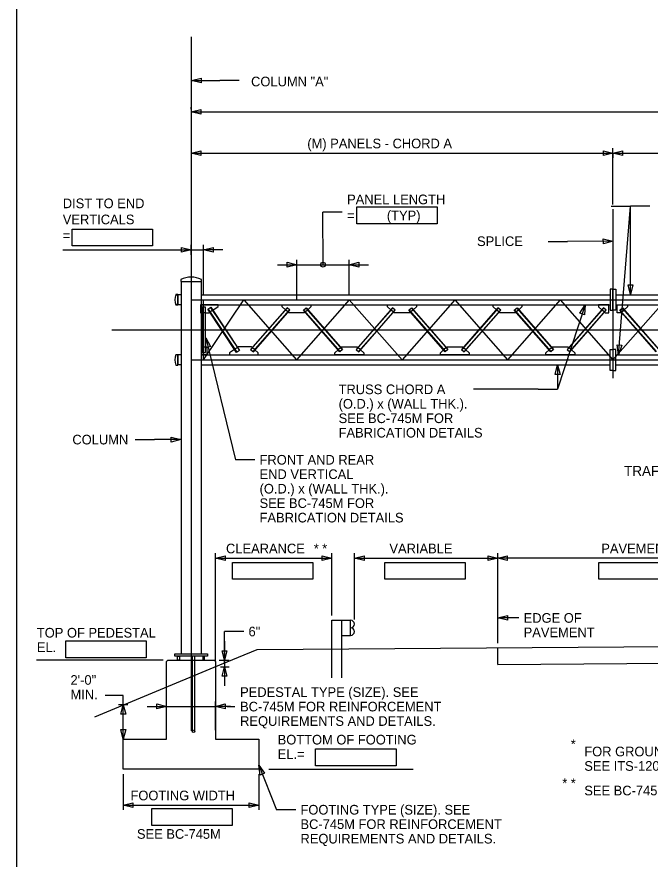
# Model space of a CAD drawing. Extents: x 3831399 to 3833095, y 499014 to 500202.
# Drawn here: x 3832280.2 to 3832471.3, y 499739.8 to 499994 of the extents above; entities that cross this region are included whole.
import ezdxf

# ---------------------------------------------------------------- set-up
doc = ezdxf.new("R2010")
doc.units = 0
for name, color, linetype in [('0-ANCHOR', 7, 'Continuous'), ('0-foundation', 7, 'Continuous'), ('0-truss', 7, 'Continuous'), ('2', 7, 'Continuous'), ('CenterLine', 7, 'Continuous'), ('Default', 7, 'Continuous'), ('DIM TXT', 7, 'Continuous'), ('grade', 7, 'Continuous'), ('x-grail', 7, 'Continuous')]:
    doc.layers.add(name, color=color, linetype=linetype)

msp = doc.modelspace()

# ---------------------------------------------------------------- linework, layer by layer
at = {"layer": '0-ANCHOR'}
for p, q in [((3832328.66, 499801.04), (3832329.23, 499801.04)), ((3832328.66, 499799.81), (3832328.66, 499801.04)), ((3832329.23, 499799.81), (3832328.66, 499799.81)), ((3832329.23, 499801.04), (3832329.23, 499799.81)), ((3832336.81, 499801.04), (3832336.24, 499801.04)), ((3832336.24, 499801.04), (3832336.24, 499799.81)), ((3832336.24, 499799.81), (3832336.81, 499799.81)), ((3832336.81, 499799.81), (3832336.81, 499801.04))]:
    msp.add_line(p, q, dxfattribs=at)
at = {"layer": '0-foundation'}
for p, q in [((3832325.35, 499799.43), (3832325.73, 499799.81)), ((3832325.35, 499797.87), (3832325.35, 499799.43)), ((3832325.73, 499799.81), (3832339.75, 499799.81)), ((3832333.12, 499778.39), (3832333.12, 499801.04)), ((3832333.87, 499778.39), (3832333.87, 499801.04)), ((3832339.75, 499799.81), (3832340.12, 499799.43)), ((3832340.12, 499799.43), (3832340.12, 499797.71)), ((3832325.35, 499776.02), (3832325.35, 499797.87)), ((3832340.12, 499797.71), (3832340.12, 499776.02)), ((3832312.28, 499766.93), (3832312.28, 499776.02)), ((3832312.28, 499776.02), (3832325.35, 499776.02)), ((3832340.12, 499776.02), (3832353.2, 499776.02)), ((3832353.2, 499776.02), (3832353.2, 499766.93)), ((3832353.2, 499766.93), (3832312.28, 499766.93))]:
    msp.add_line(p, q, dxfattribs=at)
msp.add_circle((3832333.49, 499778.39), 0.379, dxfattribs=at)
at = {"layer": '0-truss'}
for p, q in [((3832329.63, 499914.72), (3832329.63, 499914.15)), ((3832329.63, 499914.15), (3832335.84, 499914.15)), ((3832329.71, 499914.15), (3832329.71, 499801.79)), ((3832335.77, 499914.15), (3832335.77, 499801.79)), ((3832335.84, 499914.15), (3832335.84, 499914.72)), ((3832460.05, 499911.79), (3832459.19, 499911.79)), ((3832459.19, 499911.79), (3832459.19, 499905.49)), ((3832460.05, 499905.49), (3832460.05, 499911.79)), ((3832460.05, 499905.49), (3832460.05, 499911.79)), ((3832460.05, 499911.79), (3832460.9, 499911.79)), ((3832460.9, 499911.79), (3832460.9, 499905.49)), ((3832328.74, 499910.23), (3832328.17, 499910.23)), ((3832328.19, 499910.16), (3832328.74, 499910.16)), ((3832329.71, 499910.16), (3832328.74, 499910.16)), ((3832328.74, 499910.16), (3832328.74, 499907.13)), ((3832335.77, 499910.16), (3832459.19, 499910.16)), ((3832460.9, 499910.16), (3832537.29, 499910.16)), ((3832328.74, 499907.13), (3832328.19, 499907.13)), ((3832329.71, 499907.13), (3832328.74, 499907.13)), ((3832335.77, 499907.13), (3832459.19, 499907.13)), ((3832337.07, 499906.37), (3832335.98, 499906.37)), ((3832335.98, 499906.37), (3832335.98, 499892.73)), ((3832336.06, 499906.37), (3832336.06, 499892.73)), ((3832336.99, 499906.37), (3832336.99, 499892.73)), ((3832337.07, 499892.73), (3832337.07, 499906.37)), ((3832337.79, 499905.77), (3832338.7, 499906.37)), ((3832338.63, 499906.33), (3832347.32, 499893.29)), ((3832338.7, 499906.37), (3832347.39, 499893.33)), ((3832339.29, 499905.47), (3832340.91, 499906.55)), ((3832361.69, 499906.18), (3832350.71, 499893.63)), ((3832350.76, 499893.58), (3832361.74, 499906.13)), ((3832361.19, 499905.62), (3832360.21, 499906.48)), ((3832362.51, 499905.47), (3832361.69, 499906.18)), ((3832366.62, 499905.47), (3832367.44, 499906.18)), ((3832367.38, 499906.13), (3832378.36, 499893.58)), ((3832367.44, 499906.18), (3832378.42, 499893.63)), ((3832368.92, 499906.48), (3832367.94, 499905.62)), ((3832393.51, 499906.18), (3832382.53, 499893.63)), ((3832393.57, 499906.13), (3832382.59, 499893.58)), ((3832393.02, 499905.62), (3832392.03, 499906.48)), ((3832394.33, 499905.47), (3832393.51, 499906.18)), ((3832398.45, 499905.47), (3832399.27, 499906.18)), ((3832399.21, 499906.13), (3832410.19, 499893.58)), ((3832399.27, 499906.18), (3832410.25, 499893.63)), ((3832400.75, 499906.48), (3832399.76, 499905.62)), ((3832425.34, 499906.18), (3832414.36, 499893.63)), ((3832425.4, 499906.13), (3832414.42, 499893.58)), ((3832424.85, 499905.62), (3832423.86, 499906.48)), ((3832426.16, 499905.47), (3832425.34, 499906.18)), ((3832430.27, 499905.47), (3832431.09, 499906.18)), ((3832431.04, 499906.13), (3832442.02, 499893.58)), ((3832431.09, 499906.18), (3832442.07, 499893.63)), ((3832432.58, 499906.48), (3832431.59, 499905.62)), ((3832457.17, 499906.18), (3832446.19, 499893.63)), ((3832457.23, 499906.13), (3832446.25, 499893.58)), ((3832455.69, 499906.48), (3832456.67, 499905.62)), ((3832457.99, 499905.47), (3832457.17, 499906.18)), ((3832458.81, 499904.71), (3832458.81, 499907.13)), ((3832460.9, 499907.13), (3832537.29, 499907.13)), ((3832461.28, 499904.71), (3832461.28, 499907.13)), ((3832462.1, 499905.47), (3832462.92, 499906.18)), ((3832462.86, 499906.13), (3832473.84, 499893.58)), ((3832462.92, 499906.18), (3832473.9, 499893.63)), ((3832464.4, 499906.48), (3832463.42, 499905.62)), ((3832337.07, 499904.71), (3832335.98, 499904.71)), ((3832346.48, 499892.73), (3832337.79, 499905.77)), ((3832337.85, 499905.81), (3832346.54, 499892.77)), ((3832338.15, 499904.71), (3832338.39, 499904.87)), ((3832339.29, 499905.47), (3832338.39, 499904.87)), ((3832351.47, 499892.97), (3832362.45, 499905.52)), ((3832351.53, 499892.92), (3832362.51, 499905.47)), ((3832362.01, 499904.9), (3832361.19, 499905.62)), ((3832362.23, 499904.71), (3832362.01, 499904.9)), ((3832377.6, 499892.92), (3832366.62, 499905.47)), ((3832366.68, 499905.52), (3832377.66, 499892.97)), ((3832367.12, 499904.9), (3832366.9, 499904.71)), ((3832367.94, 499905.62), (3832367.12, 499904.9)), ((3832394.28, 499905.52), (3832383.3, 499892.97)), ((3832383.35, 499892.92), (3832394.33, 499905.47)), ((3832393.84, 499904.9), (3832393.02, 499905.62)), ((3832394.05, 499904.71), (3832393.84, 499904.9)), ((3832409.43, 499892.92), (3832398.45, 499905.47)), ((3832398.51, 499905.52), (3832409.49, 499892.97)), ((3832398.94, 499904.9), (3832398.73, 499904.71)), ((3832399.76, 499905.62), (3832398.94, 499904.9)), ((3832426.1, 499905.52), (3832415.12, 499892.97)), ((3832415.18, 499892.92), (3832426.16, 499905.47)), ((3832425.67, 499904.9), (3832424.85, 499905.62)), ((3832425.88, 499904.71), (3832425.67, 499904.9)), ((3832441.25, 499892.92), (3832430.27, 499905.47)), ((3832430.33, 499905.52), (3832441.31, 499892.97)), ((3832430.77, 499904.9), (3832430.56, 499904.71)), ((3832431.59, 499905.62), (3832430.77, 499904.9)), ((3832457.93, 499905.52), (3832446.95, 499892.97)), ((3832447.01, 499892.92), (3832457.99, 499905.47)), ((3832457.49, 499904.9), (3832456.67, 499905.62)), ((3832457.49, 499904.9), (3832457.71, 499904.71)), ((3832457.71, 499904.71), (3832458.81, 499904.71)), ((3832458.81, 499904.71), (3832458.81, 499904.71)), ((3832459.19, 499905.49), (3832460.05, 499905.49)), ((3832460.9, 499905.49), (3832460.05, 499905.49)), ((3832462.38, 499904.71), (3832461.28, 499904.71)), ((3832461.28, 499904.71), (3832461.28, 499904.71)), ((3832473.08, 499892.92), (3832462.1, 499905.47)), ((3832462.16, 499905.52), (3832473.14, 499892.97)), ((3832462.6, 499904.9), (3832462.38, 499904.71)), ((3832462.6, 499904.9), (3832463.42, 499905.62)), ((3832335.77, 499894.39), (3832335.98, 499894.39)), ((3832335.98, 499894.39), (3832337.07, 499894.39)), ((3832337.07, 499894.39), (3832337.45, 499894.39)), ((3832337.45, 499894.39), (3832337.45, 499891.97)), ((3832345.88, 499893.63), (3832344.29, 499892.57)), ((3832346.79, 499894.23), (3832345.88, 499893.63)), ((3832347.39, 499893.33), (3832346.48, 499892.73)), ((3832347.03, 499894.39), (3832346.79, 499894.23)), ((3832350.99, 499894.39), (3832347.03, 499894.39)), ((3832350.71, 499893.63), (3832351.53, 499892.92)), ((3832351.2, 499894.2), (3832350.99, 499894.39)), ((3832352.02, 499893.48), (3832351.2, 499894.2)), ((3832353.01, 499892.62), (3832352.02, 499893.48)), ((3832376.12, 499892.62), (3832377.11, 499893.48)), ((3832377.92, 499894.2), (3832377.11, 499893.48)), ((3832378.42, 499893.63), (3832377.6, 499892.92)), ((3832377.92, 499894.2), (3832378.14, 499894.39)), ((3832382.53, 499893.63), (3832383.35, 499892.92)), ((3832382.82, 499894.39), (3832383.03, 499894.2)), ((3832383.85, 499893.48), (3832383.03, 499894.2)), ((3832383.85, 499893.48), (3832384.83, 499892.62)), ((3832407.95, 499892.62), (3832408.93, 499893.48)), ((3832409.75, 499894.2), (3832408.93, 499893.48)), ((3832410.25, 499893.63), (3832409.43, 499892.92)), ((3832409.75, 499894.2), (3832409.97, 499894.39)), ((3832414.36, 499893.63), (3832415.18, 499892.92)), ((3832414.64, 499894.39), (3832414.86, 499894.2)), ((3832415.68, 499893.48), (3832414.86, 499894.2)), ((3832415.68, 499893.48), (3832416.66, 499892.62)), ((3832439.77, 499892.62), (3832440.76, 499893.48)), ((3832441.58, 499894.2), (3832440.76, 499893.48)), ((3832442.07, 499893.63), (3832441.25, 499892.92)), ((3832441.58, 499894.2), (3832441.79, 499894.39)), ((3832446.19, 499893.63), (3832447.01, 499892.92)), ((3832446.47, 499894.39), (3832446.68, 499894.2)), ((3832447.5, 499893.48), (3832446.68, 499894.2)), ((3832447.5, 499893.48), (3832448.49, 499892.62)), ((3832459.19, 499893.61), (3832460.05, 499893.61)), ((3832459.19, 499887.31), (3832459.19, 499893.61)), ((3832460.05, 499893.61), (3832460.05, 499887.31)), ((3832460.9, 499893.61), (3832460.05, 499893.61)), ((3832460.05, 499893.61), (3832460.05, 499887.31)), ((3832460.9, 499887.31), (3832460.9, 499893.61)), ((3832328.74, 499892.04), (3832328.17, 499892.04)), ((3832329.71, 499891.97), (3832328.74, 499891.97)), ((3832328.74, 499891.97), (3832328.74, 499888.94)), ((3832335.77, 499891.97), (3832459.19, 499891.97)), ((3832337.45, 499891.97), (3832335.77, 499891.97)), ((3832335.98, 499892.73), (3832337.07, 499892.73)), ((3832460.9, 499891.97), (3832537.29, 499891.97)), ((3832329.71, 499888.94), (3832328.74, 499888.94)), ((3832335.77, 499888.94), (3832459.19, 499888.94)), ((3832460.9, 499888.94), (3832537.29, 499888.94)), ((3832460.05, 499887.31), (3832459.19, 499887.31)), ((3832460.05, 499887.31), (3832460.9, 499887.31)), ((3832327.81, 499801.04), (3832327.81, 499801.79)), ((3832327.81, 499801.79), (3832337.66, 499801.79)), ((3832337.66, 499801.79), (3832337.66, 499801.04)), ((3832337.66, 499801.04), (3832327.81, 499801.04))]:
    msp.add_line(p, q, dxfattribs=at)
for points in [[(3832328.17, 499907.06), (3832328.74, 499907.06), (3832328.74, 499910.23)], [(3832340.91, 499906.55), (3832340.91, 499907.13), (3832335.6, 499907.13), (3832335.6, 499904.71), (3832335.98, 499904.71)], [(3832360.21, 499906.48), (3832360.21, 499907.13), (3832368.92, 499907.13), (3832368.92, 499906.48)], [(3832392.03, 499906.48), (3832392.03, 499907.13), (3832400.75, 499907.13), (3832400.75, 499906.48)], [(3832423.86, 499906.48), (3832423.86, 499907.13), (3832432.58, 499907.13), (3832432.58, 499906.48)], [(3832458.81, 499907.13), (3832455.69, 499907.13), (3832455.69, 499906.48)], [(3832461.28, 499907.13), (3832464.4, 499907.13), (3832464.4, 499906.48)], [(3832337.07, 499904.71), (3832338.15, 499904.71)], [(3832366.9, 499904.71), (3832362.23, 499904.71)], [(3832398.73, 499904.71), (3832394.05, 499904.71)], [(3832430.56, 499904.71), (3832425.88, 499904.71)], [(3832378.14, 499894.39), (3832382.82, 499894.39)], [(3832409.97, 499894.39), (3832414.64, 499894.39)], [(3832441.79, 499894.39), (3832446.47, 499894.39)], [(3832328.17, 499888.87), (3832328.74, 499888.87), (3832328.74, 499892.04)], [(3832344.29, 499892.57), (3832344.29, 499891.97), (3832353.01, 499891.97), (3832353.01, 499892.62)], [(3832384.83, 499892.62), (3832384.83, 499891.97), (3832376.12, 499891.97), (3832376.12, 499892.62)], [(3832416.66, 499892.62), (3832416.66, 499891.97), (3832407.95, 499891.97), (3832407.95, 499892.62)], [(3832448.49, 499892.62), (3832448.49, 499891.97), (3832439.77, 499891.97), (3832439.77, 499892.62)]]:
    msp.add_lwpolyline(points, dxfattribs=at)
for centre, radius, start, end in [((3832332.74, 499908.65), 6.82, 62.944, 117.056), ((3832331.28, 499908.64), 3.49, 152.944, 207.056), ((3832331.28, 499890.46), 3.49, 152.944, 207.056)]:
    msp.add_arc(centre, radius, start, end, dxfattribs=at)
at = {"layer": '2'}
msp.add_line((3832280.16, 499623.03), (3832280.16, 500187.03), dxfattribs=at)
at = {"layer": 'CenterLine'}
for p, q in [((3832332.74, 499988), (3832332.74, 499778.49)), ((3832460.05, 499935.93), (3832460.05, 499885)), ((3832332.74, 499908.64), (3832746.49, 499908.64)), ((3832336.53, 499890.46), (3832348.65, 499908.64)), ((3832336.53, 499890.46), (3832336.53, 499908.64)), ((3832348.65, 499908.64), (3832364.56, 499890.46)), ((3832380.48, 499908.64), (3832364.56, 499890.46)), ((3832380.48, 499908.64), (3832396.39, 499890.46)), ((3832412.3, 499908.64), (3832396.39, 499890.46)), ((3832412.3, 499908.64), (3832428.22, 499890.46)), ((3832444.13, 499908.64), (3832428.22, 499890.46)), ((3832444.13, 499908.64), (3832460.05, 499890.46)), ((3832475.96, 499908.64), (3832460.05, 499890.46)), ((3832308.87, 499899.55), (3832771.9, 499899.55)), ((3832332.74, 499890.46), (3832746.49, 499890.46))]:
    msp.add_line(p, q, dxfattribs=at)
at = {"layer": 'Default'}
for p, q in [((3832382.75, 499936.68), (3832407, 499936.68)), ((3832382.75, 499931.58), (3832382.75, 499936.68)), ((3832407, 499936.68), (3832407, 499931.58)), ((3832407, 499931.58), (3832382.75, 499931.58)), ((3832296.89, 499929.96), (3832321.14, 499929.96)), ((3832296.89, 499924.87), (3832296.89, 499929.96)), ((3832321.14, 499929.96), (3832321.14, 499924.87)), ((3832321.14, 499924.87), (3832296.89, 499924.87)), ((3832345.2, 499829.38), (3832369.45, 499829.38)), ((3832345.2, 499824.29), (3832345.2, 499829.38)), ((3832369.45, 499829.38), (3832369.45, 499824.29)), ((3832391.2, 499829.38), (3832415.45, 499829.38)), ((3832391.2, 499824.29), (3832391.2, 499829.38)), ((3832415.45, 499829.38), (3832415.45, 499824.29)), ((3832455.78, 499829.38), (3832480.03, 499829.38)), ((3832455.78, 499824.29), (3832455.78, 499829.38)), ((3832369.45, 499824.29), (3832345.2, 499824.29)), ((3832415.45, 499824.29), (3832391.2, 499824.29)), ((3832480.03, 499824.29), (3832455.78, 499824.29)), ((3832294.94, 499805.68), (3832319.19, 499805.68)), ((3832294.94, 499800.58), (3832294.94, 499805.68)), ((3832319.19, 499805.68), (3832319.19, 499800.58)), ((3832324.27, 499799.88), (3832286.07, 499799.88)), ((3832319.19, 499800.58), (3832294.94, 499800.58)), ((3832370.33, 499773.07), (3832394.58, 499773.07)), ((3832370.33, 499767.98), (3832370.33, 499773.07)), ((3832394.58, 499773.07), (3832394.58, 499767.98)), ((3832356.17, 499766.94), (3832399.76, 499766.94)), ((3832394.58, 499767.98), (3832370.33, 499767.98)), ((3832320.92, 499755.07), (3832345.17, 499755.07)), ((3832320.92, 499749.98), (3832320.92, 499755.07)), ((3832345.17, 499755.07), (3832345.17, 499749.98)), ((3832345.17, 499749.98), (3832320.92, 499749.98))]:
    msp.add_line(p, q, dxfattribs=at)
at = {"layer": 'DIM TXT'}
for p, q in [((3832332.83, 499974.77), (3832341.43, 499974.82)), ((3832347.25, 499974.82), (3832341.43, 499974.82)), ((3832332.74, 499966.13), (3832332.74, 499966.8)), ((3832332.74, 499965.35), (3832746.37, 499965.35)), ((3832332.74, 499962.44), (3832332.74, 499951.43)), ((3832460.05, 499937.39), (3832460.05, 499954.34)), ((3832332.74, 499952.88), (3832460.05, 499952.88)), ((3832460.05, 499952.88), (3832619.18, 499952.88)), ((3832460.05, 499952.88), (3832460.05, 499951.43)), ((3832459.5, 499936.87), (3832465.32, 499936.87)), ((3832461.75, 499892.03), (3832465.32, 499936.87)), ((3832465.35, 499910.18), (3832465.32, 499936.87)), ((3832471.14, 499936.87), (3832465.32, 499936.87)), ((3832378.36, 499935.08), (3832372.54, 499935.08)), ((3832372.56, 499919.22), (3832372.54, 499935.08)), ((3832440.48, 499926.24), (3832446.3, 499926.24)), ((3832460.05, 499926.27), (3832446.3, 499926.24)), ((3832294.02, 499923.7), (3832332.74, 499923.7)), ((3832329.83, 499924.43), (3832332.74, 499923.7)), ((3832329.83, 499922.97), (3832329.83, 499924.43)), ((3832332.74, 499923.7), (3832329.83, 499922.97)), ((3832332.74, 499922.21), (3832332.74, 499925.16)), ((3832332.74, 499923.7), (3832336.53, 499923.7)), ((3832336.53, 499910.1), (3832336.53, 499925.16)), ((3832336.53, 499923.7), (3832339.44, 499924.43)), ((3832342.35, 499923.7), (3832336.53, 499923.7)), ((3832339.44, 499922.97), (3832336.53, 499923.7)), ((3832339.44, 499924.43), (3832339.44, 499922.97)), ((3832358.82, 499919.22), (3832364.64, 499919.22)), ((3832361.73, 499919.95), (3832364.64, 499919.22)), ((3832361.73, 499918.5), (3832361.73, 499919.95)), ((3832364.64, 499919.22), (3832361.73, 499918.5)), ((3832364.64, 499908.56), (3832364.64, 499920.68)), ((3832364.64, 499919.22), (3832380.48, 499919.22)), ((3832380.48, 499910.1), (3832380.48, 499920.68)), ((3832380.48, 499919.22), (3832383.39, 499919.95)), ((3832380.48, 499919.22), (3832386.3, 499919.22)), ((3832383.39, 499918.5), (3832380.48, 499919.22)), ((3832383.39, 499919.95), (3832383.39, 499918.5)), ((3832451.66, 499907.09), (3832443.32, 499881.6)), ((3832337.22, 499897.15), (3832346.13, 499860.34)), ((3832443.33, 499888.94), (3832443.33, 499881.6)), ((3832437.51, 499881.6), (3832417.98, 499881.6)), ((3832437.5, 499881.6), (3832443.32, 499881.6)), ((3832437.51, 499881.6), (3832443.33, 499881.6)), ((3832315.83, 499866.42), (3832321.65, 499866.42)), ((3832329.63, 499866.42), (3832321.65, 499866.42)), ((3832351.95, 499860.34), (3832346.13, 499860.34)), ((3832340.12, 499799.61), (3832340.12, 499832.1)), ((3832340.12, 499830.65), (3832375.2, 499830.65)), ((3832375.2, 499813.35), (3832375.2, 499832.1)), ((3832382.07, 499812.17), (3832382.07, 499832.1)), ((3832382.07, 499830.65), (3832425.25, 499830.65)), ((3832425.25, 499805.02), (3832425.25, 499832.1)), ((3832425.25, 499806.48), (3832425.25, 499832.1)), ((3832510.09, 499830.65), (3832425.25, 499830.65)), ((3832425.26, 499812.61), (3832425.81, 499812.61)), ((3832431.63, 499812.61), (3832425.81, 499812.61)), ((3832348.61, 499808.5), (3832342.79, 499808.5)), ((3832342.81, 499798.85), (3832342.79, 499808.5)), ((3832342.81, 499805.63), (3832342.81, 499799.81)), ((3832341.2, 499799.81), (3832344.26, 499799.81)), ((3832342.81, 499799.81), (3832342.81, 499797.89)), ((3832341.6, 499797.89), (3832344.26, 499797.89)), ((3832342.81, 499797.89), (3832342.81, 499792.07)), ((3832312.28, 499789.2), (3832306.79, 499789.2)), ((3832312.28, 499785.13), (3832312.28, 499789.2)), ((3832313.65, 499786.42), (3832310.82, 499786.42)), ((3832312.28, 499776.04), (3832312.28, 499786.42)), ((3832325.35, 499778.71), (3832325.35, 499787.36)), ((3832340.12, 499778.71), (3832340.12, 499787.36)), ((3832319.53, 499785.91), (3832325.35, 499785.91)), ((3832325.35, 499785.91), (3832340.12, 499785.91)), ((3832344.64, 499785.91), (3832340.12, 499785.91)), ((3832343.67, 499785.91), (3832345.92, 499785.91)), ((3832313.73, 499776.04), (3832313.73, 499776.04)), ((3832353.2, 499768.16), (3832358.48, 499754.72)), ((3832312.28, 499765.49), (3832312.28, 499754.65)), ((3832353.2, 499765.49), (3832353.2, 499754.65)), ((3832312.28, 499756.11), (3832353.2, 499756.11)), ((3832364.3, 499754.72), (3832358.48, 499754.72))]:
    msp.add_line(p, q, dxfattribs=at)
for points in [[(3832335.74, 499974.06), (3832332.83, 499974.77), (3832335.73, 499975.51)], [(3832335.65, 499964.62), (3832332.74, 499965.35), (3832335.65, 499966.07)], [(3832335.65, 499952.16), (3832332.74, 499952.88), (3832335.65, 499953.61)], [(3832457.14, 499953.61), (3832460.05, 499952.88), (3832457.14, 499952.16)], [(3832462.96, 499952.16), (3832460.05, 499952.88), (3832462.96, 499953.61)], [(3832457.13, 499926.99), (3832460.05, 499926.27), (3832457.14, 499925.53)], [(3832466.07, 499913.09), (3832465.35, 499910.18), (3832464.62, 499913.09)], [(3832450.06, 499904.55), (3832451.66, 499907.09), (3832451.44, 499904.1)], [(3832337.19, 499894.15), (3832337.22, 499897.15), (3832338.61, 499894.5)], [(3832462.71, 499894.88), (3832461.75, 499892.03), (3832461.26, 499894.99)], [(3832442.6, 499886.03), (3832443.33, 499888.94), (3832444.06, 499886.03)], [(3832326.72, 499867.15), (3832329.63, 499866.42), (3832326.72, 499865.69)], [(3832343.03, 499829.92), (3832340.12, 499830.65), (3832343.03, 499831.38)], [(3832372.29, 499831.38), (3832375.2, 499830.65), (3832372.29, 499829.92)], [(3832384.98, 499829.92), (3832382.07, 499830.65), (3832384.98, 499831.38)], [(3832422.34, 499831.38), (3832425.25, 499830.65), (3832422.34, 499829.92)], [(3832428.16, 499829.92), (3832425.25, 499830.65), (3832428.16, 499831.38)], [(3832428.17, 499811.88), (3832425.26, 499812.61), (3832428.17, 499813.33)], [(3832343.54, 499802.72), (3832342.81, 499799.81), (3832342.08, 499802.72)], [(3832342.08, 499794.98), (3832342.81, 499797.89), (3832343.54, 499794.98)], [(3832311.55, 499783.51), (3832312.28, 499786.42), (3832313, 499783.51)], [(3832322.44, 499786.63), (3832325.35, 499785.91), (3832322.44, 499785.18)], [(3832343.03, 499785.18), (3832340.12, 499785.91), (3832343.03, 499786.63)], [(3832313, 499778.95), (3832312.28, 499776.04), (3832311.55, 499778.95)], [(3832353.58, 499765.19), (3832353.2, 499768.16), (3832354.94, 499765.72)], [(3832315.19, 499755.38), (3832312.28, 499756.11), (3832315.19, 499756.83)], [(3832350.29, 499756.83), (3832353.2, 499756.11), (3832350.29, 499755.38)]]:
    msp.add_lwpolyline(points, close=True, dxfattribs=at)
msp.add_circle((3832372.56, 499919.22), 0.727, dxfattribs=at)
at = {"layer": 'grade'}
for p, q in [((3832352.64, 499803.05), (3832510.09, 499804.17)), ((3832339.75, 499797.71), (3832352.64, 499803.05)), ((3832425.25, 499798.56), (3832425.25, 499803.57)), ((3832425.25, 499798.56), (3832510.09, 499799.16)), ((3832303.69, 499782.79), (3832339.75, 499797.71))]:
    msp.add_line(p, q, dxfattribs=at)
at = {"layer": 'x-grail'}
for p, q in [((3832375.2, 499794.54), (3832375.2, 499811.89)), ((3832375.2, 499811.89), (3832380.88, 499811.89)), ((3832378.25, 499794.54), (3832378.25, 499811.89)), ((3832380.88, 499807.35), (3832380.88, 499811.89)), ((3832378.25, 499807.35), (3832380.88, 499807.35))]:
    msp.add_line(p, q, dxfattribs=at)
for centre in [(3832380.88, 499810.76), (3832380.88, 499808.48)]:
    msp.add_arc(centre, 1.14, 270, 90, dxfattribs=at)

# ---------------------------------------------------------------- texts
at = {"layer": 'DIM TXT'}
for s, height, p in [('  COLUMN "A"', 2.9099, (3832348.68, 499973.04)), ('(M) PANELS - CHORD A', 2.9099, (3832367.8, 499954.34)), ('DIST TO END', 2.9099, (3832294.02, 499936.27)), ('PANEL LENGTH', 2.9099, (3832379.81, 499937.46)), ('VERTICALS', 2.91, (3832294.02, 499931.42)), ('=         (TYP)', 2.9099, (3832379.81, 499932.61)), ('=', 2.91, (3832294.02, 499926.57)), ('  SPLICE', 2.91, (3832416.87, 499924.84)), ('TRUSS CHORD A', 2.9099, (3832377.25, 499880.14)), ('(O.D.) x (WALL THK.).', 2.9099, (3832377.25, 499875.78)), ('SEE BC-745M FOR', 2.9099, (3832377.25, 499871.41)), ('COLUMN', 2.91, (3832296.92, 499864.97)), ('FABRICATION DETAILS', 2.9099, (3832377.25, 499867.05)), ('FRONT AND REAR', 2.9099, (3832353.4, 499858.88)), ('TRAFFIC', 3.031, (3832463.4, 499855.46)), ('END VERTICAL', 2.9099, (3832353.4, 499854.52)), ('(O.D.) x (WALL THK.).', 2.9099, (3832353.4, 499850.15)), ('SEE BC-745M FOR', 2.9099, (3832353.4, 499845.79)), ('FABRICATION DETAILS', 2.9099, (3832353.4, 499841.42)), ('CLEARANCE', 2.91, (3832343.27, 499832.1)), ('*', 2.91, (3832369.75, 499832.1)), ('*', 2.91, (3832372.3, 499832.1)), ('VARIABLE', 2.91, (3832392.58, 499832.1)), ('PAVEMENT', 2.91, (3832456.52, 499832.1)), ('EDGE OF ', 2.91, (3832433.09, 499811.15)), ('TOP OF PEDESTAL', 2.9099, (3832286.2, 499806.68)), ('6"', 2.91, (3832350.07, 499807.04)), ('PAVEMENT', 2.91, (3832433.09, 499806.79)), ('EL.', 2.91, (3832286.2, 499802.32)), ('2\'-0"', 2.91, (3832296.35, 499792.42)), ('PEDESTAL TYPE (SIZE). SEE', 2.9099, (3832347.53, 499788.76)), ('MIN.', 2.91, (3832296.35, 499788.05)), ('BC-745M FOR REINFORCEMENT', 2.9099, (3832347.53, 499784.39)), ('REQUIREMENTS AND DETAILS.', 2.9099, (3832347.53, 499780.03)), ('BOTTOM OF FOOTING', 2.9099, (3832358.86, 499774.41)), ('*', 2.91, (3832447.3, 499773.07)), ('FOR GROUND MOUNTED ENCLOSURE', 2.9099, (3832451.39, 499770.83)), ('EL.=', 2.91, (3832358.86, 499770.05)), ('SEE ITS-1201M SHEET 3.', 2.9099, (3832451.39, 499766.47)), ('*', 2.91, (3832444.75, 499761.29)), ('*', 2.91, (3832447.3, 499761.29)), ('SEE BC-745M FOR CLEARANCE REQUIREMENTS.', 2.9099, (3832451.39, 499759.05)), ('FOOTING WIDTH', 2.9099, (3832314.45, 499757.56)), ('FOOTING TYPE (SIZE). SEE', 2.9099, (3832365.75, 499753.26)), ('BC-745M FOR REINFORCEMENT', 2.9099, (3832365.75, 499748.9)), ('SEE BC-745M', 2.9099, (3832316.4, 499745.95)), ('REQUIREMENTS AND DETAILS.', 2.9099, (3832365.75, 499744.53))]:
    msp.add_text(s, height=height, dxfattribs=at).set_placement(p)

doc.saveas('drawing.dxf')
